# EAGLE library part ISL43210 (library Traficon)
Intersil SPDT single supply switch
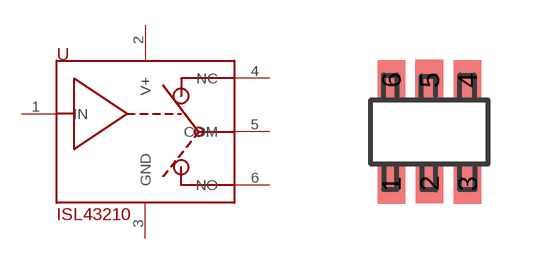
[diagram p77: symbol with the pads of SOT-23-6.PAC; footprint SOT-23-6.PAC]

Designator prefix U

## ISL43210  [SOT-23-6.PAC]
1  IN
2  V+
3  GND
4  NC
5  COM
6  NO

## Footprint SOT-23-6.PAC (pad centres in mm)
smd 0.686 x 0.991: 1 -0.953,-1.295; 2 0,-1.283; 3 0.953,-1.295; 4 0.953,1.295; 6 -0.953,1.295
smd 0.7 x 1: 5 0,1.3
